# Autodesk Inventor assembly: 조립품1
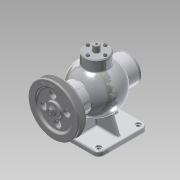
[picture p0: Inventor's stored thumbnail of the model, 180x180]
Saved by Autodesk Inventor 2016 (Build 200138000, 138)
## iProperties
Created: 2017-01
Part Number: 조립품1
Material: 일반
Document SubType Name: Assembly
Designer: Administrator
Author: Administrator
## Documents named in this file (19)
- C:\Users\Administrator\Desktop\470130V1004\470130V1004\조립품1.iam
- C:\Users\Administrator\Desktop\470130V1004\470130V1004\본체.ipt
- C:\Users\Administrator\Desktop\470130V1004\470130V1004\편심축.ipt
- C:\Users\Administrator\Desktop\470130V1004\470130V1004\부시.ipt
- C:\Users\Administrator\Desktop\470130V1004\470130V1004\베어링- 6202.ipt
- KS B 2023 - 6202 - 15 x 35 x 11 - 7.8.ipt
- C:\Users\Administrator\Desktop\470130V1004\470130V1004\앞커버.ipt
- C:\Users\Administrator\Desktop\470130V1004\470130V1004\오일실 15 30 7.ipt
- C:\Users\Administrator\Desktop\470130V1004\470130V1004\키 4 x 4 x 12.ipt
- C:\Users\Administrator\Desktop\470130V1004\470130V1004\V-벨트풀리.ipt
- C:\Users\Administrator\Desktop\470130V1004\470130V1004\너트 M8.ipt
- C:\Users\Administrator\Desktop\470130V1004\470130V1004\볼트 M4 x 16.ipt
- C:\Users\Administrator\Desktop\470130V1004\470130V1004\멈춤링- 15 x 1.ipt
- C:\Users\Administrator\Desktop\470130V1004\470130V1004\멈춤링- 35x1.6.ipt
- KS B 1336 - 35x1.6.ipt
- C:\Users\Administrator\Desktop\470130V1004\470130V1004\뒤커버.ipt
- C:\Users\Administrator\Desktop\470130V1004\470130V1004\슬라이드.ipt
- C:\Users\Administrator\Desktop\470130V1004\470130V1004\상부커버.ipt
- C:\Users\Administrator\Desktop\470130V1004\470130V1004\볼트 M4 x 12.ipt
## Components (16 placed, 5 different names)
1. KS B 2023 - 6202 - 15 x 35 x 11 - 7.8:1
2. V-벨트풀리:1
3. KS B 1336 - 35x1.6:1
4. KS B 2023 - 6202 - 15 x 35 x 11 - 7.8:2
5. ISO 4762 M4 x 16:1
6. ISO 4762 M4 x 16:2
7. ISO 4762 M4 x 16:3
8. ISO 4762 M4 x 16:4
9. ISO 4762 M4 x 16:5
10. ISO 4762 M4 x 16:6
11. ISO 4762 M4 x 16:7
12. ISO 4762 M4 x 16:8
13. KS B 1021 - 에 따름 ISO 1207 - 미터 A  M 4 x 12:1
14. KS B 1021 - 에 따름 ISO 1207 - 미터 A  M 4 x 12:2
15. KS B 1021 - 에 따름 ISO 1207 - 미터 A  M 4 x 12:3
16. KS B 1021 - 에 따름 ISO 1207 - 미터 A  M 4 x 12:4
